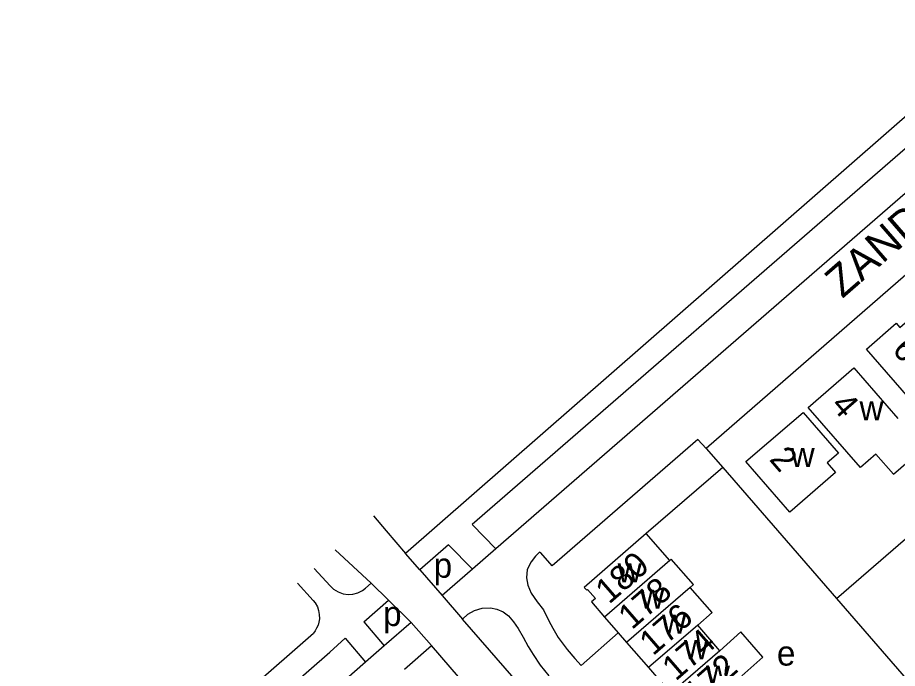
# Model space of a CAD drawing. Extents: x 155854 to 157362, y 383621 to 384685.
# Drawn here: x 156185.4 to 156327, y 384343.2 to 384447.9 of the extents above; entities that cross this region are included whole.
import ezdxf

# ---------------------------------------------------------------- set-up
doc = ezdxf.new("R2010")
doc.units = 0
for name, color, linetype in [('BLT_Basislijn', 7, 'Continuous'), ('BLT_Bebouwing', 7, 'Continuous'), ('BLT_Centroide', 7, 'Continuous'), ('BLT_Huisnummer', 7, 'Continuous'), ('BLT_Huisnummer_ tussenligend', 7, 'Continuous'), ('BLT_Onderverdeling_panden', 7, 'Continuous'), ('BLT_Straatnaam', 7, 'Continuous'), ('BLT_Vlakafsluiter', 7, 'Continuous')]:
    doc.layers.add(name, color=color, linetype=linetype)

msp = doc.modelspace()

# ---------------------------------------------------------------- linework, layer by layer
at = {"layer": 'BLT_Basislijn'}
for p, q in [((156354.83, 384455.2), (156247.82, 384361.74)), ((156357.48, 384452.21), (156258.53, 384366.4)), ((156317.2, 384354.46), (156387.22, 384415.29)), ((156298.87, 384375.56), (156286.57, 384364.92)), ((156298.87, 384375.56), (156317.2, 384354.46)), ((156242.69, 384367.77), (156244.72, 384365.38)), ((156244.72, 384365.38), (156247.82, 384361.74)), ((156258.53, 384366.4), (156262.39, 384362.48)), ((156254.75, 384363.11), (156250.12, 384359.1)), ((156254.75, 384363.11), (156258.61, 384359.19)), ((156250.12, 384359.1), (156247.82, 384361.74)), ((156250.12, 384359.1), (156253.72, 384354.95)), ((156230.47, 384356.94), (156232.97, 384354.14)), ((156242.31, 384356.95), (156245.09, 384354.24)), ((156241.13, 384350.73), (156245.09, 384354.24)), ((156245.09, 384354.24), (156248.76, 384350.63)), ((156317.2, 384354.46), (156338.19, 384330.3)), ((156295.38, 384307.06), (156257, 384351.17)), ((156241.13, 384350.73), (156244.41, 384346.85)), ((156248.76, 384350.63), (156244.41, 384346.85)), ((156132.85, 384261.87), (156233.02, 384348.89)), ((156235.65, 384345.87), (156238.14, 384348.08)), ((156238.14, 384348.08), (156241.39, 384344.23)), ((156288.49, 384304.89), (156251.99, 384346.91)), ((156189.84, 384306.07), (156235.65, 384345.87)), ((156244.41, 384346.85), (156241.39, 384344.23)), ((156241.39, 384344.23), (156193.31, 384302.46))]:
    msp.add_line(p, q, dxfattribs=at)
for points in [[(156365.23, 384451.81), (156311.98, 384405.55), (156262.39, 384362.48)], [(156366.24, 384439.44), (156296.22, 384378.61)], [(156296.21, 384378.61), (156294.85, 384380.08), (156271.43, 384359.73), (156269.6, 384361.83), (156269.39, 384361.96), (156268.74, 384361.31), (156268.03, 384360.38), (156267.38, 384359.15), (156267.31, 384357.79), (156267.52, 384356.64), (156268.03, 384355.34), (156269.03, 384353.97), (156270.04, 384352.68), (156270.9, 384350.88), (156271.55, 384349.73), (156272.41, 384348.22), (156273.85, 384346.28), (156275.08, 384344.85), (156276.07, 384343.72), (156282.04, 384348.97)], [(156296.22, 384378.61), (156298.87, 384375.56)], [(156262.39, 384362.48), (156258.61, 384359.19)], [(156236.53, 384362.3), (156242.31, 384356.95)], [(156235.69, 384356.5), (156233.15, 384359.31)], [(156258.61, 384359.19), (156253.72, 384354.95)], [(156235.69, 384356.5), (156236.24, 384355.98), (156236.99, 384355.54), (156237.79, 384355.23), (156238.6, 384355.12), (156239.37, 384355.16), (156240.17, 384355.38), (156240.89, 384355.78), (156241.4, 384356.13), (156242.31, 384356.95)], [(156232.97, 384354.14), (156233.27, 384353.79), (156233.64, 384353.13), (156233.82, 384352.56), (156233.95, 384351.92), (156233.99, 384351.22), (156233.89, 384350.66), (156233.77, 384350.18), (156233.53, 384349.69), (156233.31, 384349.28), (156233.02, 384348.89)], [(156257, 384351.17), (156257.88, 384351.94), (156258.91, 384352.56), (156260.15, 384352.93), (156261.52, 384352.97), (156262.51, 384352.77), (156263.55, 384352.35), (156264.38, 384351.69), (156265.2, 384350.74), (156265.95, 384349.66), (156266.78, 384348.25), (156267.56, 384346.76), (156268.35, 384345.48), (156269.51, 384343.74), (156270.87, 384342.04)], [(156247.66, 384343.12), (156251.99, 384346.91)]]:
    msp.add_lwpolyline(points, dxfattribs=at)
at = {"layer": 'BLT_Bebouwing'}
for p, q in [((156326.34, 384374.47), (156331.17, 384378.67)), ((156323.52, 384377.72), (156326.34, 384374.47)), ((156290.34, 384360.59), (156286.57, 384364.92)), ((156298.42, 384346.08), (156294.86, 384350.17))]:
    msp.add_line(p, q, dxfattribs=at)
for points in [[(156329.96, 384400.31), (156337.04, 384392.15), (156339.83, 384388.94), (156332.5, 384382.56), (156329.9, 384385.55), (156322.01, 384394.61), (156326.79, 384398.76), (156327.38, 384398.07), (156329.96, 384400.31)], [(156323.52, 384377.72), (156321.03, 384375.55), (156312.61, 384385.23), (156319.95, 384391.61)], [(156319.95, 384391.61), (156327.04, 384383.46)], [(156310.01, 384382.82), (156311.81, 384384.39), (156317.49, 384377.86), (156315.68, 384376.29), (156317.03, 384374.74), (156309.69, 384368.37), (156302.61, 384376.52), (156310.01, 384382.82)], [(156286.57, 384364.92), (156276.59, 384356.24), (156276.99, 384355.8), (156277.14, 384355.95), (156278.39, 384354.49), (156277.74, 384353.92), (156279.87, 384351.47)], [(156293.65, 384356.25), (156294.15, 384356.74), (156290.6, 384360.81), (156290.34, 384360.59)], [(156294.86, 384350.17), (156297.16, 384352.21), (156293.65, 384356.25)], [(156279.87, 384351.47), (156282.04, 384348.97)], [(156282.04, 384348.97), (156283.38, 384347.43)], [(156301.93, 384342.04), (156305.35, 384345.03), (156301.81, 384349.1), (156298.42, 384346.08)], [(156283.38, 384347.43), (156286.92, 384343.36)], [(156286.92, 384343.36), (156290.47, 384339.26)]]:
    msp.add_lwpolyline(points, dxfattribs=at)
at = {"layer": 'BLT_Onderverdeling_panden'}
for p, q in [((156290.34, 384360.59), (156279.87, 384351.47)), ((156293.65, 384356.25), (156283.38, 384347.43)), ((156294.86, 384350.17), (156286.92, 384343.36)), ((156298.42, 384346.08), (156290.47, 384339.26))]:
    msp.add_line(p, q, dxfattribs=at)
at = {"layer": 'BLT_Vlakafsluiter'}
for p, q in [((156253.72, 384354.95), (156257, 384351.17)), ((156251.99, 384346.91), (156248.76, 384350.63))]:
    msp.add_line(p, q, dxfattribs=at)

# ---------------------------------------------------------------- texts
at = {"layer": 'BLT_Centroide'}
for s, p in [('w', (156320.89, 384383.12)), ('w', (156309.81, 384375.62)), ('p', (156252.36, 384357.83)), ('w', (156281.97, 384357.06)), ('w', (156285.59, 384352.84)), ('p', (156244.22, 384350.06)), ('w', (156289.12, 384348.81)), ('w', (156292.66, 384344.72)), ('e', (156307.6, 384343.69)), ('w', (156296.18, 384340.62))]:
    msp.add_text(s, height=4, dxfattribs=at).set_placement(p)
at = {"layer": 'BLT_Huisnummer'}
for s, rotation, p in [('6', 310.9758, (156325.99, 384394.4)), ('4', 310.9758, (156316.12, 384385.47)), ('2', 310.9758, (156306.24, 384376.8)), ('180', 40.9877, (156280.58, 384353.46)), ('174', 40.9877, (156291.31, 384341.09))]:
    msp.add_text(s, height=4, rotation=rotation, dxfattribs=at).set_placement(p)
at = {"layer": 'BLT_Huisnummer_ tussenligend'}
for s, p in [('178', (156284.25, 384349.34)), ('176', (156287.65, 384345.15)), ('172', (156294.85, 384337.04))]:
    msp.add_text(s, height=4, rotation=40.9877, dxfattribs=at).set_placement(p)
at = {"layer": 'BLT_Straatnaam'}
msp.add_text('ZANDGOLF', height=5, rotation=40.9818, dxfattribs=at).set_placement((156318.13, 384402.65))

doc.saveas('drawing.dxf')
